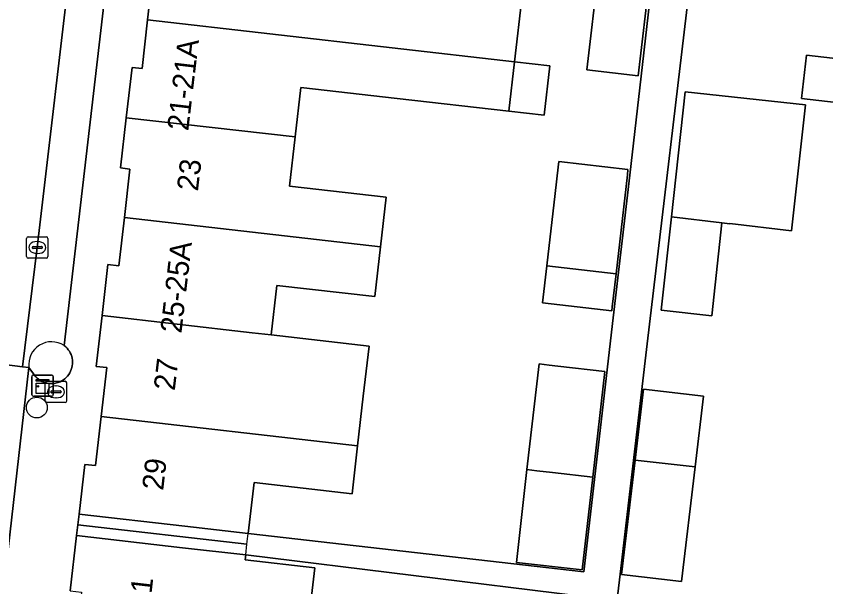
# Model space of a CAD drawing. Extents: x 161692 to 162379, y 380760 to 381678.
# Drawn here: x 162217.92 to 162255.9, y 381045.72 to 381072.52 of the extents above; entities that cross this region are included whole.
import ezdxf

# ---------------------------------------------------------------- set-up
doc = ezdxf.new("R2010")
doc.units = 0
for name, color, linetype in [('IMGEO_Boom', 7, 'Continuous'), ('IMGEO_Brandkraan', 7, 'Continuous'), ('IMGEO_Erf', 7, 'Continuous'), ('IMGEO_Groenvoorziening', 7, 'Continuous'), ('IMGEO_Kast', 7, 'Continuous'), ('IMGEO_Kolk', 7, 'Continuous'), ('IMGEO_Pand', 7, 'Continuous'), ('IMGEO_Pand_nummerreeks', 7, 'Continuous'), ('IMGEO_Pand_overbouw', 7, 'Continuous'), ('IMGEO_Parkeervlak_open', 7, 'Continuous'), ('IMGEO_Rijbaan_lokaal_open', 7, 'Continuous'), ('IMGEO_Voetpad_open', 7, 'Continuous')]:
    doc.layers.add(name, color=color, linetype=linetype)

msp = doc.modelspace()

# ---------------------------------------------------------------- linework, layer by layer
at = {"layer": 'IMGEO_Boom'}
msp.add_circle((162218.885, 381054.138), 0.489, dxfattribs=at)
at = {"layer": 'IMGEO_Brandkraan'}
for p, q in [((162219.284, 381054.448), (162219.284, 381055.3)), ((162219.359, 381055.374), (162220.211, 381055.374)), ((162219.772, 381055.154), (162219.797, 381055.154)), ((162220.285, 381055.3), (162220.285, 381054.448)), ((162219.543, 381054.868), (162219.543, 381054.88)), ((162219.981, 381054.831), (162219.583, 381054.831)), ((162219.586, 381054.917), (162219.984, 381054.917)), ((162220.027, 381054.88), (162220.027, 381054.868)), ((162220.211, 381054.374), (162219.359, 381054.374)), ((162219.795, 381054.594), (162219.77, 381054.594))]:
    msp.add_line(p, q, dxfattribs=at)
for points in [[(162219.284, 381054.448), (162219.284, 381055.3)], [(162219.359, 381055.374), (162220.211, 381055.374)], [(162220.285, 381055.3), (162220.285, 381054.448)], [(162220.211, 381054.374), (162219.359, 381054.374)]]:
    msp.add_lwpolyline(points, dxfattribs=at)
for centre, radius, start, end in [((162219.361, 381055.298), 0.0765, 91.552, 178.448), ((162219.361, 381055.298), 0.0765, 91.552, 178.448), ((162220.209, 381055.298), 0.0765, 1.552, 88.448), ((162220.209, 381055.298), 0.0765, 1.552, 88.448), ((162219.583, 381054.877), 0.0403, 85.8775, 175.7526), ((162219.58, 381054.867), 0.0366, 178.938, 274.7102), ((162219.984, 381054.874), 0.043, 264.8664, 352.4533), ((162219.988, 381054.879), 0.0386, 1.7309, 96.639), ((162219.361, 381054.45), 0.0765, 181.552, 268.448), ((162219.361, 381054.45), 0.0765, 181.552, 268.448), ((162220.209, 381054.45), 0.0765, 271.552, 358.448), ((162220.209, 381054.45), 0.0765, 271.552, 358.448)]:
    msp.add_arc(centre, radius, start, end, dxfattribs=at)
for centre, major_axis, ratio, start_param, end_param in [((162219.771, 381054.874), (-0.387, 0.002), 0.722429, 4.712389, 7.853982), ((162219.796, 381054.874), (-0.39, 0.002), 0.717154, 1.570796, 4.712389)]:
    msp.add_ellipse(centre, major_axis=major_axis, ratio=ratio, start_param=start_param, end_param=end_param, dxfattribs=at)
at = {"layer": 'IMGEO_Erf'}
for points in [[(162245.313, 381084.153), (162248.761, 381083.759), (162248.207, 381079.093), (162247.65, 381074.397), (162247.094, 381069.716), (162244.689, 381070.001), (162245.244, 381074.673), (162245.803, 381079.375), (162244.769, 381079.496)], [(162250.552, 381058.452), (162248.185, 381058.711), (162248.663, 381063.087), (162249.311, 381068.967), (162254.942, 381068.347), (162254.291, 381062.439), (162251.406, 381062.787), (162251.405, 381062.771), (162251.029, 381062.814)], [(162242.812, 381060.796), (162243.2, 381064.184), (162243.343, 381065.433), (162243.372, 381065.688), (162246.621, 381065.317), (162246.592, 381065.062), (162246.061, 381060.424), (162245.883, 381058.87), (162245.861, 381058.677), (162242.613, 381059.048)], [(162242.449, 381056.189), (162242.925, 381056.135), (162243.335, 381056.088), (162245.535, 381055.837), (162244.967, 381050.869), (162244.468, 381046.512), (162241.383, 381046.865), (162241.881, 381051.223)], [(162246.322, 381046.302), (162246.952, 381051.672), (162247.344, 381055.007), (162250.158, 381054.676), (162249.767, 381051.349), (162249.136, 381045.972)]]:
    msp.add_lwpolyline(points, close=True, dxfattribs=at)
for points in [[(162262.757, 381073.661), (162249.668, 381075.215), (162247.52, 381057.127), (162246.249, 381046.311), (162245.475, 381039.702), (162244.896, 381034.012), (162244.259, 381027.764), (162243.52, 381021.774), (162246.411, 381021.417), (162260.68, 381019.761)], [(162241.65, 381073.494), (162241.294, 381070.377), (162242.949, 381070.178), (162242.685, 381067.866), (162241.029, 381068.055), (162235.793, 381068.653), (162231.275, 381069.169), (162231.009, 381066.844), (162230.745, 381064.54), (162235.279, 381064.022), (162235.012, 381061.689), (162234.745, 381059.351), (162230.148, 381059.877), (162229.882, 381057.55), (162234.472, 381057.023), (162234.204, 381054.677), (162233.937, 381052.341), (162233.68, 381050.091), (162229.075, 381050.618), (162228.801, 381048.222), (162244.556, 381046.417), (162245.93, 381058.352), (162246.701, 381065.049), (162247.237, 381069.698), (162247.777, 381074.382)], [(162262.087, 381067.805), (162254.763, 381068.647), (162254.997, 381070.685), (162262.321, 381069.843)], [(162244.421, 381045.287), (162228.686, 381047.214), (162228.659, 381046.98), (162231.924, 381046.606), (162231.665, 381044.343)]]:
    msp.add_lwpolyline(points, dxfattribs=at)
at = {"layer": 'IMGEO_Groenvoorziening'}
msp.add_lwpolyline([(162218.512, 381056.025), (162218.724, 381055.724), (162218.775, 381055.651), (162218.833, 381055.583), (162218.896, 381055.52), (162218.964, 381055.463), (162219.038, 381055.413), (162219.115, 381055.369), (162219.197, 381055.332), (162219.281, 381055.303), (162219.367, 381055.281), (162219.455, 381055.268), (162219.544, 381055.262), (162219.633, 381055.264), (162219.721, 381055.274), (162219.809, 381055.292), (162219.894, 381055.318), (162219.977, 381055.351), (162220.056, 381055.391), (162220.132, 381055.438), (162220.202, 381055.492), (162220.268, 381055.552), (162220.328, 381055.618), (162220.383, 381055.689), (162220.43, 381055.764), (162220.471, 381055.843), (162220.504, 381055.926), (162220.53, 381056.011), (162220.548, 381056.098), (162220.559, 381056.187), (162220.561, 381056.276), (162220.555, 381056.365), (162220.542, 381056.453), (162220.521, 381056.539), (162220.492, 381056.623), (162220.455, 381056.705), (162220.412, 381056.782), (162220.361, 381056.856), (162220.305, 381056.925), (162220.242, 381056.988), (162220.174, 381057.046), (162220.162, 381057.055)], dxfattribs=at)
msp.add_arc((162219.579, 381056.152), 1.075, 57.1353, 186.813, dxfattribs=at)
at = {"layer": 'IMGEO_Kast'}
for p, q in [((162218.654, 381054.741), (162218.654, 381055.582)), ((162218.654, 381055.582), (162218.654, 381054.741)), ((162218.729, 381055.666), (162219.57, 381055.666)), ((162219.57, 381055.666), (162218.729, 381055.666)), ((162219.654, 381055.591), (162219.654, 381054.75)), ((162219.654, 381054.75), (162219.654, 381055.591)), ((162219.579, 381054.666), (162218.738, 381054.666)), ((162218.738, 381054.666), (162219.579, 381054.666))]:
    msp.add_line(p, q, dxfattribs=at)
for points in [[(162218.849, 381055.456), (162219.449, 381055.456), (162219.449, 381055.371), (162218.849, 381055.371), (162218.849, 381055.456)], [(162218.849, 381055.281), (162219.449, 381055.281), (162219.449, 381054.792), (162218.849, 381054.792), (162218.849, 381055.281)]]:
    msp.add_lwpolyline(points, dxfattribs=at)
msp.add_circle((162218.933, 381055.13), 0.0377, dxfattribs=at)
for centre, start, end in [((162218.732, 381055.588), 92.4484, 184.2845), ((162218.732, 381055.588), 92.4484, 184.2845), ((162219.576, 381055.588), 2.4484, 94.2845), ((162219.576, 381055.588), 2.4484, 94.2845), ((162218.732, 381054.744), 182.4484, 274.2845), ((162218.732, 381054.744), 182.4484, 274.2845), ((162219.576, 381054.744), 272.4484, 4.2845), ((162219.576, 381054.744), 272.4484, 4.2845)]:
    msp.add_arc(centre, 0.0779, start, end, dxfattribs=at)
at = {"layer": 'IMGEO_Kolk'}
for p, q in [((162218.407, 381061.228), (162218.407, 381062.08)), ((162218.482, 381062.154), (162219.334, 381062.154)), ((162218.895, 381061.934), (162218.92, 381061.934)), ((162219.408, 381062.08), (162219.408, 381061.228)), ((162218.666, 381061.648), (162218.666, 381061.66)), ((162219.104, 381061.611), (162218.706, 381061.611)), ((162218.709, 381061.697), (162219.107, 381061.697)), ((162219.15, 381061.66), (162219.15, 381061.648)), ((162219.334, 381061.154), (162218.482, 381061.154)), ((162218.918, 381061.374), (162218.893, 381061.374))]:
    msp.add_line(p, q, dxfattribs=at)
for points in [[(162218.407, 381061.228), (162218.407, 381062.08)], [(162218.482, 381062.154), (162219.334, 381062.154)], [(162219.408, 381062.08), (162219.408, 381061.228)], [(162219.334, 381061.154), (162218.482, 381061.154)]]:
    msp.add_lwpolyline(points, dxfattribs=at)
for centre, radius, start, end in [((162218.484, 381062.078), 0.0765, 91.552, 178.448), ((162218.484, 381062.078), 0.0765, 91.552, 178.448), ((162219.332, 381062.078), 0.0765, 1.552, 88.448), ((162219.332, 381062.078), 0.0765, 1.552, 88.448), ((162218.706, 381061.657), 0.0403, 85.8775, 175.7526), ((162218.703, 381061.647), 0.0366, 178.938, 274.7102), ((162219.107, 381061.654), 0.043, 264.8664, 352.4533), ((162219.111, 381061.659), 0.0386, 1.7309, 96.639), ((162218.484, 381061.23), 0.0765, 181.552, 268.448), ((162218.484, 381061.23), 0.0765, 181.552, 268.448), ((162219.332, 381061.23), 0.0765, 271.552, 358.448), ((162219.332, 381061.23), 0.0765, 271.552, 358.448)]:
    msp.add_arc(centre, radius, start, end, dxfattribs=at)
for centre, major_axis, ratio, start_param, end_param in [((162218.894, 381061.654), (-0.387, 0.002), 0.722429, 4.712389, 7.853982), ((162218.919, 381061.654), (-0.39, 0.002), 0.717154, 1.570796, 4.712389)]:
    msp.add_ellipse(centre, major_axis=major_axis, ratio=ratio, start_param=start_param, end_param=end_param, dxfattribs=at)
at = {"layer": 'IMGEO_Pand'}
for points in [[(162224.082, 381072.35), (162241.294, 381070.377), (162241.65, 381073.494), (162236.411, 381074.092), (162236.327, 381073.318), (162231.815, 381073.834), (162232.084, 381076.182), (162224.148, 381077.092), (162223.874, 381074.696), (162224.344, 381074.642)], [(162247.65, 381074.397), (162245.531, 381074.639), (162245.244, 381074.673), (162244.689, 381070.001), (162247.094, 381069.716)], [(162241.294, 381070.377), (162224.082, 381072.35), (162223.82, 381070.058), (162223.353, 381070.112), (162223.083, 381067.75), (162231.009, 381066.844), (162231.275, 381069.169), (162235.793, 381068.653), (162241.029, 381068.055)], [(162262.321, 381069.843), (162254.997, 381070.685), (162254.763, 381068.647), (162262.087, 381067.805)], [(162241.294, 381070.377), (162241.029, 381068.055), (162242.685, 381067.866), (162242.949, 381070.178)], [(162254.942, 381068.347), (162249.311, 381068.967), (162248.663, 381063.087), (162251.029, 381062.814), (162251.405, 381062.771), (162251.406, 381062.787), (162254.291, 381062.439)], [(162235.012, 381061.689), (162235.279, 381064.022), (162230.745, 381064.54), (162231.009, 381066.844), (162223.083, 381067.75), (162222.813, 381065.388), (162223.255, 381065.337), (162222.995, 381063.065)], [(162242.812, 381060.796), (162246.061, 381060.424), (162246.592, 381065.062), (162246.621, 381065.317), (162243.372, 381065.688), (162243.343, 381065.433), (162243.2, 381064.184)], [(162235.012, 381061.689), (162222.995, 381063.065), (162222.736, 381060.797), (162222.219, 381060.856), (162221.945, 381058.462), (162228.99, 381057.652), (162229.882, 381057.55), (162230.148, 381059.877), (162234.745, 381059.351)], [(162251.029, 381062.814), (162248.663, 381063.087), (162248.185, 381058.711), (162250.552, 381058.452)], [(162246.061, 381060.424), (162242.812, 381060.796), (162242.613, 381059.048), (162245.861, 381058.677), (162245.883, 381058.87)], [(162229.882, 381057.55), (162228.99, 381057.652), (162221.945, 381058.462), (162221.671, 381056.072), (162222.172, 381056.015), (162221.908, 381053.712), (162233.937, 381052.341), (162234.204, 381054.677), (162234.472, 381057.023)], [(162241.881, 381051.223), (162242.349, 381051.168), (162243.087, 381051.084), (162244.967, 381050.869), (162245.535, 381055.837), (162243.335, 381056.088), (162242.925, 381056.135), (162242.449, 381056.189)], [(162246.952, 381051.672), (162249.767, 381051.349), (162250.158, 381054.676), (162247.344, 381055.007)], [(162233.937, 381052.341), (162221.908, 381053.712), (162221.645, 381051.412), (162221.131, 381051.471), (162220.864, 381049.133), (162225.832, 381048.563), (162228.801, 381048.222), (162229.075, 381050.618), (162233.68, 381050.091)], [(162249.767, 381051.349), (162246.952, 381051.672), (162246.322, 381046.302), (162249.136, 381045.972)], [(162244.967, 381050.869), (162243.087, 381051.084), (162242.349, 381051.168), (162241.881, 381051.223), (162241.383, 381046.865), (162244.468, 381046.512)], [(162228.659, 381046.98), (162228.686, 381047.214), (162225.717, 381047.555), (162220.749, 381048.125), (162220.452, 381045.528), (162220.977, 381045.467), (162220.717, 381043.188), (162232.693, 381041.821), (162234.137, 381041.655), (162234.409, 381044.028), (162232.964, 381044.194), (162231.665, 381044.343), (162231.924, 381046.606)]]:
    msp.add_lwpolyline(points, close=True, dxfattribs=at)
at = {"layer": 'IMGEO_Pand_overbouw'}
for points in [[(162228.801, 381048.222), (162225.832, 381048.563), (162220.864, 381049.133), (162220.806, 381048.629), (162228.744, 381047.718)], [(162228.686, 381047.214), (162228.744, 381047.718), (162220.806, 381048.629), (162220.749, 381048.125), (162225.717, 381047.555)]]:
    msp.add_lwpolyline(points, close=True, dxfattribs=at)
at = {"layer": 'IMGEO_Parkeervlak_open'}
for points in [[(162222.8, 381094.372), (162222.682, 381094.384), (162222.002, 381088.091), (162220.579, 381075.909), (162218.907, 381061.654), (162218.219, 381056.054), (162218.512, 381056.025)], [(162220.162, 381057.055), (162224.378, 381093.251)]]:
    msp.add_lwpolyline(points, dxfattribs=at)
msp.add_arc((162219.579, 381056.152), 1.075, 57.1353, 186.813, dxfattribs=at)
at = {"layer": 'IMGEO_Rijbaan_lokaal_open'}
for points in [[(162219.396, 381094.73), (162218.628, 381088.239), (162217.21, 381076.083), (162215.568, 381062.131), (162214.924, 381056.471), (162218.219, 381056.054), (162218.907, 381061.654), (162220.579, 381075.909), (162222.002, 381088.091), (162222.682, 381094.384)], [(162213.306, 381045.133), (162213.598, 381045.093), (162216.935, 381044.734), (162217.228, 381044.718), (162218.512, 381056.025), (162218.219, 381056.054), (162214.924, 381056.471), (162214.64, 381056.476)]]:
    msp.add_lwpolyline(points, close=True, dxfattribs=at)
at = {"layer": 'IMGEO_Voetpad_open'}
for points in [[(162224.378, 381093.251), (162220.162, 381057.055), (162220.174, 381057.046), (162220.242, 381056.988), (162220.305, 381056.925), (162220.361, 381056.856), (162220.412, 381056.782), (162220.455, 381056.705), (162220.492, 381056.623), (162220.521, 381056.539), (162220.542, 381056.453), (162220.555, 381056.365), (162220.561, 381056.276), (162220.559, 381056.187), (162220.548, 381056.098), (162220.53, 381056.011), (162220.504, 381055.926), (162220.471, 381055.843), (162220.43, 381055.764), (162220.383, 381055.689), (162220.328, 381055.618), (162220.268, 381055.552), (162220.202, 381055.492), (162220.132, 381055.438), (162220.056, 381055.391), (162219.977, 381055.351), (162219.894, 381055.318), (162219.809, 381055.292), (162219.721, 381055.274), (162219.633, 381055.264), (162219.544, 381055.262), (162219.455, 381055.268), (162219.367, 381055.281), (162219.281, 381055.303), (162219.197, 381055.332), (162219.115, 381055.369), (162219.038, 381055.413), (162218.964, 381055.463), (162218.896, 381055.52), (162218.833, 381055.583), (162218.775, 381055.651), (162218.724, 381055.724), (162218.512, 381056.025), (162217.228, 381044.718)], [(162260.68, 381019.761), (162246.411, 381021.417), (162243.52, 381021.774), (162244.259, 381027.764), (162244.896, 381034.012), (162245.475, 381039.702), (162246.249, 381046.311), (162247.52, 381057.127), (162249.668, 381075.215), (162262.757, 381073.661)], [(162220.452, 381045.528), (162220.749, 381048.125), (162220.806, 381048.629), (162220.864, 381049.133), (162221.131, 381051.471), (162221.645, 381051.412), (162221.908, 381053.712), (162222.172, 381056.015), (162221.671, 381056.072), (162221.945, 381058.462), (162222.219, 381060.856), (162222.736, 381060.797), (162222.995, 381063.065), (162223.255, 381065.337), (162222.813, 381065.388), (162223.083, 381067.75), (162223.353, 381070.112), (162223.82, 381070.058), (162224.082, 381072.35), (162224.344, 381074.642)], [(162247.777, 381074.382), (162247.237, 381069.698), (162246.701, 381065.049), (162245.93, 381058.352), (162244.556, 381046.417), (162228.801, 381048.222), (162225.832, 381048.563), (162220.864, 381049.133), (162220.806, 381048.629), (162220.749, 381048.125), (162225.717, 381047.555), (162228.686, 381047.214), (162244.421, 381045.287)]]:
    msp.add_lwpolyline(points, dxfattribs=at)

# ---------------------------------------------------------------- texts
at = {"layer": 'IMGEO_Pand_nummerreeks'}
for s, rotation, p in [('21-21A', 83.2794, (162225.989, 381067.105)), ('23', 83.381, (162226.443, 381064.273)), ('25-25A', 83.3825, (162225.668, 381057.601)), ('27', 83.3825, (162225.356, 381054.903)), ('29', 83.381, (162224.812, 381050.217)), ('31', 83.4112, (162224.179, 381044.636))]:
    msp.add_text(s, height=1, rotation=rotation, dxfattribs=at).set_placement(p)

doc.saveas('drawing.dxf')
